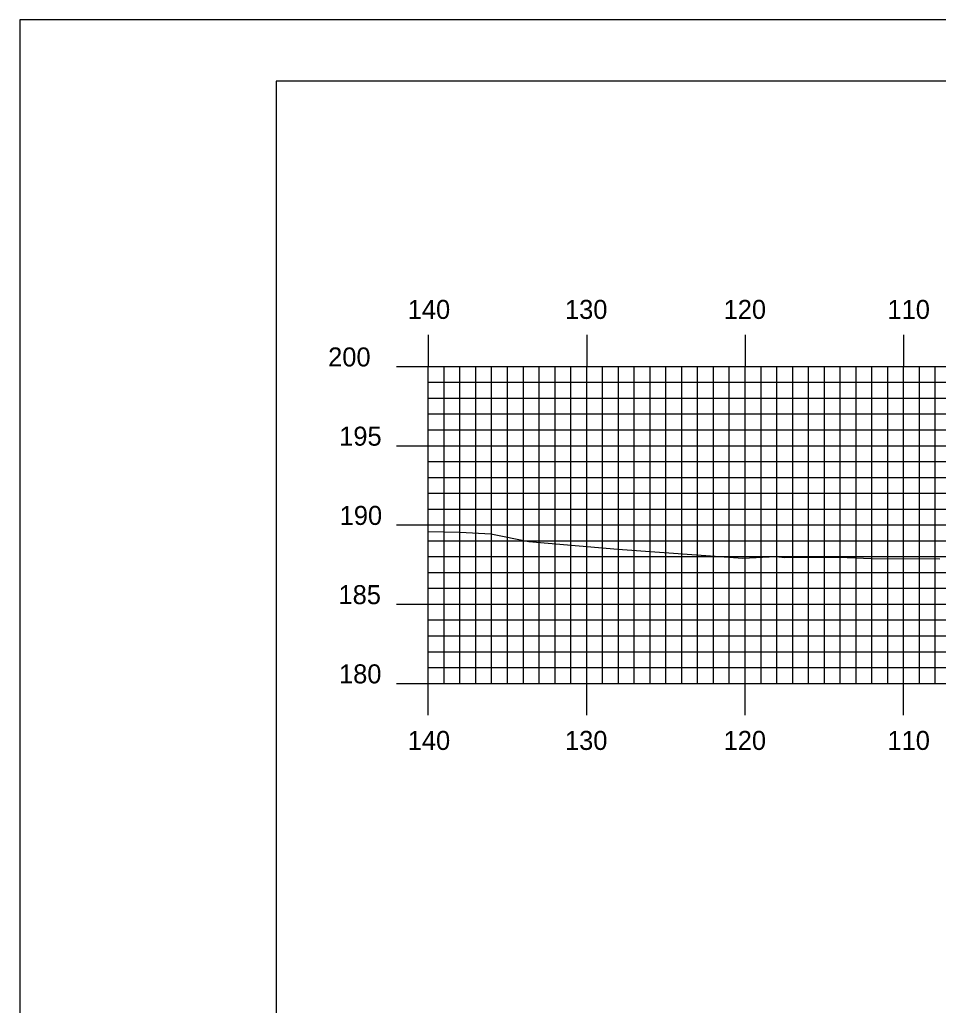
# Model space of a CAD drawing. Extents: x 1825147 to 1825490, y 442591 to 442811.
# Drawn here: x 1825146.6 to 1825204.6, y 442748.4 to 442810.5 of the extents above; entities that cross this region are included whole.
import ezdxf

# ---------------------------------------------------------------- set-up
doc = ezdxf.new("R2010")
doc.units = 0
for name, color, linetype in [('BORDER', 7, 'Continuous'), ('H_V ANNOTATION', 7, 'Continuous'), ('MAJOR', 7, 'Continuous'), ('MINOR', 7, 'Continuous'), ('PLOT BOUNDARY', 7, 'Continuous'), ('S_Roadway_Centerline', 7, 'Continuous')]:
    doc.layers.add(name, color=color, linetype=linetype)

msp = doc.modelspace()

# ---------------------------------------------------------------- linework, layer by layer
at = {"layer": 'BORDER'}
msp.add_lwpolyline([(1825162.761, 442596.665), (1825482.761, 442596.665), (1825482.761, 442806.665), (1825162.761, 442806.665)], close=True, dxfattribs=at)
at = {"layer": 'MAJOR'}
for p, q in [((1825172.361, 442790.669), (1825172.361, 442788.665)), ((1825182.361, 442790.669), (1825182.361, 442788.665)), ((1825192.361, 442790.669), (1825192.361, 442788.665)), ((1825202.361, 442790.669), (1825202.361, 442788.665)), ((1825170.357, 442788.665), (1825172.361, 442788.665)), ((1825172.361, 442788.665), (1825452.361, 442788.665)), ((1825172.361, 442768.665), (1825172.361, 442788.665)), ((1825172.361, 442768.665), (1825172.361, 442788.665)), ((1825172.361, 442788.665), (1825452.361, 442788.665)), ((1825182.361, 442768.665), (1825182.361, 442788.665)), ((1825192.361, 442768.665), (1825192.361, 442788.665)), ((1825202.361, 442768.665), (1825202.361, 442788.665)), ((1825170.357, 442783.665), (1825172.361, 442783.665)), ((1825172.361, 442783.665), (1825452.361, 442783.665)), ((1825170.357, 442778.665), (1825172.361, 442778.665)), ((1825172.361, 442778.665), (1825452.361, 442778.665)), ((1825170.357, 442773.665), (1825172.361, 442773.665)), ((1825172.361, 442773.665), (1825452.361, 442773.665)), ((1825170.357, 442768.665), (1825172.361, 442768.665)), ((1825172.361, 442768.665), (1825452.361, 442768.665)), ((1825172.361, 442768.665), (1825452.361, 442768.665)), ((1825172.361, 442766.661), (1825172.361, 442768.665)), ((1825182.361, 442766.661), (1825182.361, 442768.665)), ((1825192.361, 442766.661), (1825192.361, 442768.665)), ((1825202.361, 442766.661), (1825202.361, 442768.665))]:
    msp.add_line(p, q, dxfattribs=at)
at = {"layer": 'MINOR'}
for p, q in [((1825173.361, 442768.665), (1825173.361, 442788.665)), ((1825174.361, 442768.665), (1825174.361, 442788.665)), ((1825175.361, 442768.665), (1825175.361, 442788.665)), ((1825176.361, 442768.665), (1825176.361, 442788.665)), ((1825177.361, 442768.665), (1825177.361, 442788.665)), ((1825178.361, 442768.665), (1825178.361, 442788.665)), ((1825179.361, 442768.665), (1825179.361, 442788.665)), ((1825180.361, 442768.665), (1825180.361, 442788.665)), ((1825181.361, 442768.665), (1825181.361, 442788.665)), ((1825183.361, 442768.665), (1825183.361, 442788.665)), ((1825184.361, 442768.665), (1825184.361, 442788.665)), ((1825185.361, 442768.665), (1825185.361, 442788.665)), ((1825186.361, 442768.665), (1825186.361, 442788.665)), ((1825187.361, 442768.665), (1825187.361, 442788.665)), ((1825188.361, 442768.665), (1825188.361, 442788.665)), ((1825189.361, 442768.665), (1825189.361, 442788.665)), ((1825190.361, 442768.665), (1825190.361, 442788.665)), ((1825191.361, 442768.665), (1825191.361, 442788.665)), ((1825193.361, 442768.665), (1825193.361, 442788.665)), ((1825194.361, 442768.665), (1825194.361, 442788.665)), ((1825195.361, 442768.665), (1825195.361, 442788.665)), ((1825196.361, 442768.665), (1825196.361, 442788.665)), ((1825197.361, 442768.665), (1825197.361, 442788.665)), ((1825198.361, 442768.665), (1825198.361, 442788.665)), ((1825199.361, 442768.665), (1825199.361, 442788.665)), ((1825200.361, 442768.665), (1825200.361, 442788.665)), ((1825201.361, 442768.665), (1825201.361, 442788.665)), ((1825203.361, 442768.665), (1825203.361, 442788.665)), ((1825204.361, 442768.665), (1825204.361, 442788.665)), ((1825172.361, 442787.665), (1825452.361, 442787.665)), ((1825172.361, 442787.665), (1825174.365, 442787.665)), ((1825172.361, 442786.665), (1825452.361, 442786.665)), ((1825172.361, 442786.665), (1825174.365, 442786.665)), ((1825172.361, 442785.665), (1825452.361, 442785.665)), ((1825172.361, 442785.665), (1825174.365, 442785.665)), ((1825172.361, 442784.665), (1825452.361, 442784.665)), ((1825172.361, 442784.665), (1825174.365, 442784.665)), ((1825172.361, 442782.665), (1825452.361, 442782.665)), ((1825172.361, 442782.665), (1825174.365, 442782.665)), ((1825172.361, 442781.665), (1825452.361, 442781.665)), ((1825172.361, 442781.665), (1825174.365, 442781.665)), ((1825172.361, 442780.665), (1825452.361, 442780.665)), ((1825172.361, 442780.665), (1825174.365, 442780.665)), ((1825172.361, 442779.665), (1825452.361, 442779.665)), ((1825172.361, 442779.665), (1825174.365, 442779.665)), ((1825172.361, 442777.665), (1825452.361, 442777.665)), ((1825172.361, 442777.665), (1825174.365, 442777.665)), ((1825172.361, 442776.665), (1825452.361, 442776.665)), ((1825172.361, 442776.665), (1825174.365, 442776.665)), ((1825172.361, 442775.665), (1825452.361, 442775.665)), ((1825172.361, 442775.665), (1825174.365, 442775.665)), ((1825172.361, 442774.665), (1825452.361, 442774.665)), ((1825172.361, 442774.665), (1825174.365, 442774.665)), ((1825172.361, 442772.665), (1825452.361, 442772.665)), ((1825172.361, 442772.665), (1825174.365, 442772.665)), ((1825172.361, 442771.665), (1825452.361, 442771.665)), ((1825172.361, 442771.665), (1825174.365, 442771.665)), ((1825172.361, 442770.665), (1825452.361, 442770.665)), ((1825172.361, 442770.665), (1825174.365, 442770.665)), ((1825172.361, 442769.665), (1825452.361, 442769.665)), ((1825172.361, 442769.665), (1825174.365, 442769.665))]:
    msp.add_line(p, q, dxfattribs=at)
at = {"layer": 'PLOT BOUNDARY'}
msp.add_lwpolyline([(1825146.574, 442590.547), (1825486.574, 442590.547), (1825486.574, 442810.547), (1825146.574, 442810.547)], close=True, dxfattribs=at)
at = {"layer": 'S_Roadway_Centerline'}
msp.add_lwpolyline([(1825172.361, 442778.255), (1825174.373, 442778.202), (1825176.306, 442778.1), (1825178.7, 442777.615), (1825184.327, 442777.144), (1825192.207, 442776.567), (1825194.288, 442776.677), (1825194.857, 442776.603), (1825198.276, 442776.634), (1825200.366, 442776.551), (1825204.657, 442776.532)], dxfattribs=at)

# ---------------------------------------------------------------- texts
at = {"layer": 'H_V ANNOTATION'}
for s, p in [('140', (1825171.066, 442791.665)), ('130', (1825180.991, 442791.665)), ('120', (1825191.002, 442791.665)), ('110', (1825201.344, 442791.665)), ('200', (1825166.042, 442788.665)), ('195', (1825166.739, 442783.665)), ('190', (1825166.771, 442778.665)), ('185', (1825166.696, 442773.665)), ('180', (1825166.728, 442768.665)), ('140', (1825171.066, 442764.465)), ('130', (1825180.991, 442764.465)), ('120', (1825191.002, 442764.465)), ('110', (1825201.344, 442764.465))]:
    msp.add_text(s, height=1.2, dxfattribs=at).set_placement(p)
at = {"layer": 'MAJOR'}
msp.add_text('-', height=0.012, dxfattribs=at).set_placement((1825172.352, 442768.665))

doc.saveas('drawing.dxf')
